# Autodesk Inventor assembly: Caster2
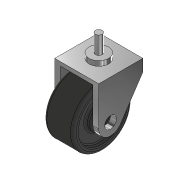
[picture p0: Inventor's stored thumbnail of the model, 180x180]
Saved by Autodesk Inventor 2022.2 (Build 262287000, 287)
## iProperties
Created: 2021-12
Part Number: Caster2
Document SubType Name: Assembly
Designer: taeku
Author: taeku
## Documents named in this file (3)
- D:\Inventor\Tutorial 2\第9回 Generative Design\Caster.iam
- D:\Inventor\Tutorial 2\第9回 Generative Design\Wheel.ipt
- D:\Inventor\Tutorial 2\第9回 Generative Design\Holder.ipt
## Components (2 placed, 2 different names)
1. Wheel:1 — 回転:2
2. Holder:1 — 回転:2
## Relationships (1: RevoluteJoint 1)
- 回転:2 [RevoluteJoint]: Wheel:1 ↔ Holder:1
